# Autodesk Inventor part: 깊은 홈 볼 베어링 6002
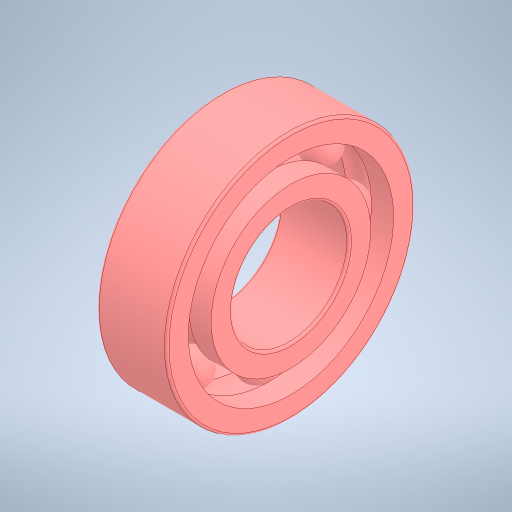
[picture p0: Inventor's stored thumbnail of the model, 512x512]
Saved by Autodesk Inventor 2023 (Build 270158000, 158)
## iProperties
Created: 2025-10
Part Number: 깊은 홈 볼 베어링 6002
Material: 강철, 연강
Description: 깊은 그루브 볼 베어링
Document SubType Name: Modeling
Designer: home
Density: 7.85 g/cm^3
Appearance: 기본값
Author: jhkim
Sending System: Autodesk Inventor 2026
Preprocessor: ST-DEVELOPER v20.1
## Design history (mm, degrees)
sketch "스케치1"
  geometry: 1 further point
feature "Solid1"
feature "Solid1:1"
feature "Solid1:2"
feature "Solid1:3"
feature "Solid1:4"
feature "Solid1:5"
feature "Solid1:6"
feature "Solid1:7"
feature "Solid1:8"
feature "Solid1:9"
node "솔리드1"
node "솔리드2"
node "솔리드3"
node "솔리드4"
node "솔리드5"
node "솔리드6"
node "솔리드7"
node "솔리드8"
node "솔리드9"
node "솔리드10"
